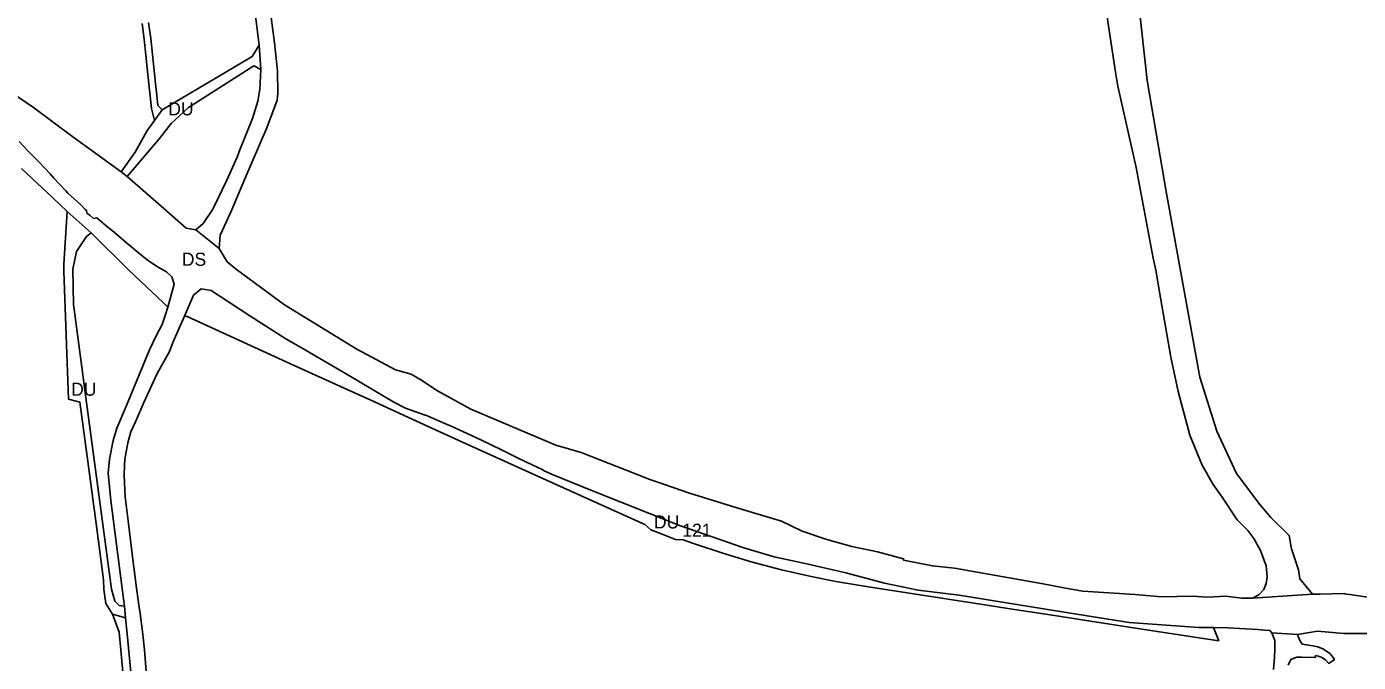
# Model space of a CAD drawing. Extents: x -521047 to -518054, y -1194945 to -1189555.
# Drawn here: x -520050 to -519036, y -1193041 to -1192557 of the extents above; entities that cross this region are included whole.
import ezdxf

# ---------------------------------------------------------------- set-up
doc = ezdxf.new("R2010")
doc.units = 0
for name, color, linetype in [('90310013', 7, 'Continuous'), ('90310023', 7, 'Continuous'), ('90320013', 7, 'Continuous'), ('ID_navrh', 7, 'Continuous')]:
    doc.layers.add(name, color=color, linetype=linetype)

msp = doc.modelspace()

# ---------------------------------------------------------------- linework, layer by layer
at = {"layer": '90310013'}
for points in [[(-519952.4, -1192628.52), (-519958.27, -1192636.72), (-519967.07, -1192652.71), (-519977.84, -1192667.57), (-519973.13, -1192671.04), (-519965.83, -1192662.43), (-519948.49, -1192642.24), (-519939.66, -1192630.65), (-519926.45, -1192618.64), (-519876.72, -1192586.93), (-519871.43, -1192589.64), (-519872.8, -1192571.21), (-519878.04, -1192579.76), (-519946.53, -1192620.31), (-519952.4, -1192628.52)], [(-519975.28, -1192998.31), (-519979.39, -1192997.86), (-519982.68, -1192994.68), (-519985.11, -1192985.35), (-520003.51, -1192847.12), (-520012.68, -1192778.14), (-520013.94, -1192768.6), (-520014.48, -1192741.68), (-520011.85, -1192728.35), (-520004.15, -1192716.76), (-520000.53, -1192714.15), (-520018.8, -1192697.81), (-520021.45, -1192737.96), (-520021.35, -1192743.3), (-520017.97, -1192840.72), (-520009.13, -1192843.07), (-520004.11, -1192880.48), (-519996.02, -1192941.34), (-519991.11, -1192978.26), (-519991.05, -1192985.7), (-519989.51, -1192996.39), (-519984.44, -1193004.38), (-519974.42, -1193007.26), (-519975.28, -1192998.31)], [(-519089.11, -1193043.23), (-519087.08, -1193038.9), (-519082.67, -1193037.22), (-519078.8, -1193037.27), (-519068.53, -1193037.41), (-519068.36, -1193036.01), (-519066.12, -1193036.54), (-519063.71, -1193037.53), (-519060.88, -1193039.35), (-519058.32, -1193041.95), (-519054.02, -1193039.03), (-519054.97, -1193037.51), (-519057.59, -1193034.55), (-519062.38, -1193031.14), (-519066.57, -1193029.49), (-519070.56, -1193028.61), (-519078.69, -1193027.26), (-519080.51, -1193024.08), (-519082.01, -1193019.86), (-519101.64, -1193018.75), (-519099.43, -1193024.53), (-519099.27, -1193031.44), (-519099.54, -1193037.16), (-519100.42, -1193046.7)]]:
    msp.add_lwpolyline(points, dxfattribs=at)
at = {"layer": '90310023'}
for points in [[(-519961.77, -1192554.51), (-519960.25, -1192566.55), (-519958.97, -1192578.79), (-519956.62, -1192600.81), (-519955.64, -1192609.73), (-519954.63, -1192619.45), (-519952.4, -1192628.52)], [(-519952.4, -1192628.52), (-519946.53, -1192620.31), (-519949.86, -1192616.95), (-519950.67, -1192609.2), (-519951.65, -1192600.27), (-519954, -1192578.27), (-519955.28, -1192565.98), (-519956.83, -1192553.76)], [(-520053.58, -1192665.11), (-520045.5, -1192672.63), (-520030.09, -1192687.16), (-520018.8, -1192697.81), (-520000.53, -1192714.15), (-519971.98, -1192742.48), (-519945.61, -1192767.46), (-519942.19, -1192770.64), (-519937.48, -1192753.23), (-519939.19, -1192747.54), (-519943.24, -1192743.8), (-519949.52, -1192740.3), (-519951.15, -1192739.21), (-519954.66, -1192736.87), (-519958.02, -1192734.64), (-519965.96, -1192728.13), (-519969.72, -1192725.06), (-519973.72, -1192721.78), (-519982.87, -1192713.75), (-519984.4, -1192712.41), (-519989.28, -1192708.76), (-519996.17, -1192702.74), (-519998.74, -1192703.05), (-520001.45, -1192700.96), (-520003.74, -1192699.2), (-520003.86, -1192699.11), (-520004.13, -1192696.91), (-520005.16, -1192696.15), (-520008.78, -1192692.58), (-520018.25, -1192683.72), (-520019.9, -1192682.17), (-520029, -1192672.3), (-520031.93, -1192669.12), (-520040.3, -1192660.32), (-520048.69, -1192651.55), (-520055.38, -1192644.58)], [(-519142.04, -1193024.85), (-519146.2, -1193014.77), (-519157.21, -1193014.6), (-519210.29, -1193010.83), (-519267.67, -1193001.68), (-519339.75, -1192990.06), (-519370.98, -1192986.14), (-519396.52, -1192980.8), (-519425.99, -1192972.98), (-519454.77, -1192966.51), (-519480.63, -1192960.73), (-519503.57, -1192953.95), (-519551.94, -1192937.22), (-519621.37, -1192909.57), (-519648.88, -1192898.4), (-519655.13, -1192895.45), (-519657.29, -1192894.4), (-519668.57, -1192888.89), (-519677.43, -1192884.57), (-519687.55, -1192879.63), (-519697.18, -1192875), (-519707.74, -1192869.98), (-519717.04, -1192865.69), (-519727.02, -1192861.14), (-519727.74, -1192860.81), (-519735.5, -1192857.45), (-519745.77, -1192853), (-519746.17, -1192852.82), (-519761.29, -1192847.68), (-519770.17, -1192843), (-519803.79, -1192823.02), (-519842.92, -1192800.19), (-519852.37, -1192794.85), (-519879.73, -1192777.34), (-519909.25, -1192757.84), (-519916.81, -1192756.78), (-519922.71, -1192761.62), (-519929.51, -1192777.57), (-519927.45, -1192777.89), (-519848.77, -1192813.79), (-519819.07, -1192827.26), (-519805.68, -1192833.36), (-519788.21, -1192841.3), (-519752.94, -1192857.37), (-519717.76, -1192873.41), (-519653.99, -1192902.46), (-519579.08, -1192936.23), (-519574.51, -1192940.18), (-519567.2, -1192943.06), (-519555.74, -1192947.57), (-519549.76, -1192947.78), (-519542.07, -1192950.61), (-519518.93, -1192958.37), (-519498.2, -1192964.55), (-519474.87, -1192970.68), (-519452.37, -1192975.76), (-519433.72, -1192979.51), (-519407.22, -1192983.93), (-519379.4, -1192988.21), (-519316.79, -1192997.86), (-519302.57, -1193000.06), (-519267.23, -1193005.51), (-519239.74, -1193009.74), (-519195.48, -1193016.56), (-519142.04, -1193024.85)], [(-519984.44, -1193004.38), (-519979.35, -1193018.09), (-519975.45, -1193059.33)], [(-519969.42, -1193059.31), (-519973.19, -1193019.52), (-519974.42, -1193007.26), (-519984.44, -1193004.38)]]:
    msp.add_lwpolyline(points, dxfattribs=at)
at = {"layer": '90320013'}
for points in [[(-519875.66, -1192546.69), (-519874.18, -1192558.92), (-519872.8, -1192571.21), (-519871.43, -1192589.64), (-519872.16, -1192604.77), (-519873.78, -1192613.72), (-519877.84, -1192627.03), (-519887.28, -1192650.8), (-519889.55, -1192656.44), (-519897.61, -1192674.42), (-519907.66, -1192695.43), (-519907.96, -1192696.03), (-519915.4, -1192706.96), (-519920.96, -1192711.64), (-519903.22, -1192725.88), (-519902.42, -1192715.87), (-519899.04, -1192708.67), (-519893.83, -1192697.06), (-519883.59, -1192673.01), (-519866.95, -1192634.05), (-519859.02, -1192613.05), (-519858.51, -1192607.7), (-519858.8, -1192590.58), (-519861, -1192569.32), (-519864.74, -1192540.33)], [(-519228.6, -1192539.54), (-519220.59, -1192591.78), (-519218.96, -1192602.21), (-519205.04, -1192664.2), (-519192.03, -1192733.27), (-519190.11, -1192742.39), (-519186.41, -1192763.61), (-519178.57, -1192808.82), (-519173.07, -1192834.93), (-519164.09, -1192868.23), (-519154.59, -1192891.1), (-519146.39, -1192905.76), (-519139.52, -1192915.5), (-519128.05, -1192932.59), (-519120.04, -1192940.87), (-519115.42, -1192946.77), (-519110.36, -1192955.97), (-519106.04, -1192967.67), (-519105.28, -1192976), (-519105.89, -1192981.11), (-519107.69, -1192985.77), (-519111.6, -1192989.77), (-519116.45, -1192992.35), (-519070.65, -1192989.38), (-519080.25, -1192977.67), (-519081.47, -1192970.65), (-519082.2, -1192968.42), (-519086.7, -1192954.76), (-519086.92, -1192953.51), (-519088.52, -1192944.47), (-519102.51, -1192930.9), (-519110.71, -1192920.84), (-519128.56, -1192897.44), (-519143.51, -1192865.04), (-519156.37, -1192823.91), (-519181.88, -1192684.13), (-519196.54, -1192598), (-519202.8, -1192540.04)], [(-519026.96, -1192991.92), (-519042.16, -1192989.58), (-519044.97, -1192989.14), (-519046.88, -1192988.85), (-519064.74, -1192989.25), (-519070.65, -1192989.38), (-519116.45, -1192992.35), (-519124.43, -1192992.31), (-519136.83, -1192990.7), (-519150.69, -1192991.58), (-519162.1, -1192990.71), (-519186.01, -1192991.26), (-519205.81, -1192989.39), (-519225.72, -1192988.29), (-519245.61, -1192987.01), (-519258.65, -1192984.65), (-519275.79, -1192981.35), (-519338.88, -1192970.21), (-519343.21, -1192969.49), (-519360.04, -1192967.68), (-519382.21, -1192963.28), (-519382, -1192962.28), (-519401.78, -1192957), (-519421.33, -1192953.08), (-519440.39, -1192947.55), (-519459.24, -1192941.4), (-519475.01, -1192933.77), (-519509.74, -1192923.15), (-519544.98, -1192912.28), (-519569.95, -1192903.63), (-519575.19, -1192901.81), (-519578.65, -1192900.59), (-519578.96, -1192900.47), (-519627.56, -1192881.34), (-519646.77, -1192875.82), (-519711.44, -1192848.38), (-519736.95, -1192834.43), (-519749.68, -1192825.91), (-519756.9, -1192821.72), (-519768.91, -1192818.48), (-519798.31, -1192802.61), (-519853.29, -1192768.82), (-519889.94, -1192741.9), (-519897, -1192736.11), (-519903.22, -1192725.88), (-519920.96, -1192711.64), (-519928.14, -1192710.54), (-519945.35, -1192695.43), (-519973.13, -1192671.04), (-519977.84, -1192667.57), (-520014.61, -1192640.84), (-520044.56, -1192618.55), (-520061.16, -1192607.27)], [(-520055.38, -1192644.58), (-520048.69, -1192651.55), (-520040.3, -1192660.32), (-520031.93, -1192669.12), (-520029, -1192672.3), (-520019.9, -1192682.17), (-520018.25, -1192683.72), (-520008.78, -1192692.58), (-520005.16, -1192696.15), (-520004.13, -1192696.91), (-520003.86, -1192699.11), (-520003.74, -1192699.2), (-520001.45, -1192700.96), (-519998.74, -1192703.05), (-519996.17, -1192702.74), (-519989.28, -1192708.76), (-519984.4, -1192712.41), (-519982.87, -1192713.75), (-519973.72, -1192721.78), (-519969.72, -1192725.06), (-519965.96, -1192728.13), (-519958.02, -1192734.64), (-519954.66, -1192736.87), (-519951.15, -1192739.21), (-519949.52, -1192740.3), (-519943.24, -1192743.8), (-519939.19, -1192747.54), (-519937.48, -1192753.23), (-519942.19, -1192770.64), (-519944.02, -1192776.33), (-519946.43, -1192783.81), (-519950.92, -1192792.01), (-519956.08, -1192803.22), (-519973.79, -1192845.48), (-519981.06, -1192862.78), (-519983.86, -1192872.26), (-519986.6, -1192886.41), (-519987.63, -1192897.15), (-519985.67, -1192917.82), (-519976.99, -1192984.86), (-519975.28, -1192998.31), (-519974.42, -1193007.26), (-519973.19, -1193019.52), (-519969.42, -1193059.31)], [(-519957.98, -1193057.97), (-519959.95, -1193031.63), (-519961.59, -1193017.82), (-519963.23, -1193004.02), (-519964.4, -1192997.62), (-519966.28, -1192982.61), (-519968.01, -1192968.78), (-519968.79, -1192962.75), (-519970.58, -1192948.05), (-519972.14, -1192935.43), (-519974.75, -1192915.01), (-519975.59, -1192898.9), (-519975.27, -1192891.17), (-519975.08, -1192886.33), (-519972.67, -1192873.95), (-519970.35, -1192865.66), (-519966.94, -1192857.93), (-519960.56, -1192843.19), (-519950.26, -1192821.29), (-519941.05, -1192804.31), (-519938.48, -1192797.62), (-519929.51, -1192777.57), (-519922.71, -1192761.62), (-519916.81, -1192756.78), (-519909.25, -1192757.84), (-519879.73, -1192777.34), (-519852.37, -1192794.85), (-519842.92, -1192800.19), (-519803.79, -1192823.02), (-519770.17, -1192843), (-519761.29, -1192847.68), (-519746.17, -1192852.82), (-519745.77, -1192853), (-519735.5, -1192857.45), (-519727.74, -1192860.81), (-519727.02, -1192861.14), (-519717.04, -1192865.69), (-519707.74, -1192869.98), (-519697.18, -1192875), (-519687.55, -1192879.63), (-519677.43, -1192884.57), (-519668.57, -1192888.89), (-519657.29, -1192894.4), (-519655.13, -1192895.45), (-519648.88, -1192898.4), (-519621.37, -1192909.57), (-519551.94, -1192937.22), (-519503.57, -1192953.95), (-519480.63, -1192960.73), (-519454.77, -1192966.51), (-519425.99, -1192972.98), (-519396.52, -1192980.8), (-519370.98, -1192986.14), (-519339.75, -1192990.06), (-519267.67, -1193001.68), (-519210.29, -1193010.83), (-519157.21, -1193014.6), (-519146.2, -1193014.77), (-519135.18, -1193014.94), (-519126.21, -1193015.42), (-519112.45, -1193016.14), (-519107.3, -1193016.61), (-519103.14, -1193016.99), (-519101.64, -1193018.75), (-519082.01, -1193019.86), (-519067.01, -1193017.55), (-519046.96, -1193019.18), (-519025.46, -1193019.32)]]:
    msp.add_lwpolyline(points, dxfattribs=at)

# ---------------------------------------------------------------- texts
at = {"layer": '90310013'}
for rotation, p in [(0, (-519941.92, -1192624.56)), (360, (-520015.86, -1192838.15))]:
    msp.add_text('DU', height=10, rotation=rotation, dxfattribs=at).set_placement(p)
at = {"layer": '90310023'}
msp.add_text('DU', height=10, rotation=0, dxfattribs=at).set_placement((-519572.12, -1192939.24))
at = {"layer": '90320013'}
msp.add_text('DS', height=10, rotation=0, dxfattribs=at).set_placement((-519931.58, -1192739.16))
at = {"layer": 'ID_navrh'}
msp.add_text('121', height=10, rotation=0, dxfattribs=at).set_placement((-519550.55, -1192945.56))

doc.saveas('drawing.dxf')
